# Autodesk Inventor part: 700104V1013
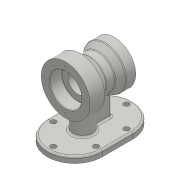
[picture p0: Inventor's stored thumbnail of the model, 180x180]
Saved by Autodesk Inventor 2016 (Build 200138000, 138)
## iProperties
Created: 2020-01
Part Number: 700104V1013
Material: Generic
Document SubType Name: Modeling
Designer: woori
Density: 1 g/cm^3
Appearance: Default
Author: woori
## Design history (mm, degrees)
sketch "스케치1"
  geometry: L1 (-25, 0)-(25, 0); L2 (-25, -45)-(25, -45); L3 (25, 45)-(-25, 45); A1 r 45 centre (-25, 0) between (-25, 45) and (-25, -45); A2 r 45 centre (25, 0) between (25, -45) and (25, 45); 2 further points
  constraints: 8 end point, 4 point on circle, 4 tangent, 2 centre point, 1 coincident, 1 horizontal, 1 midpoint, 1 parallel
  dimensions: "d0" = 50 distance of L3.start L3.end; "d1" = 45 radius of A1
extrude "돌출1" new body sketch "스케치1" distance "d2" = 10; taper "d3" = 0 deg
sketch "스케치2"
  geometry: L1 (0, 80)-(0, 0); L2 (0, 80)-(40, 80); L3 (40, 80)-(40, 115); L4 (40, 115)-(24, 115); L5 (24, 115)-(13.289, 107.5); L6 (13.289, 107.5)-(-1.103, 107.5); L7 (-1.103, 107.5)-(-16, 120); L8 (-16, 120)-(-40, 120); L9 (-40, 120)-(-40, 80); L10 (-40, 80)-(0, 80); L11 (-25, 0)-(-70, 0) reference; L12 (-70, 0)-(-70, 19.736)
  constraints: 22 end point, 4 perpendicular, 2 parallel, 2 vertical, 1 horizontal, 1 point on line
  dimensions: "d4" = 80 distance of L1.start L1.end; "d5" = 35 deg angle of L6 L5; "d6" = 40 deg angle of L6 L7; "d7" = 16 distance of L3.end L4.end; "d8" = 24 distance of L7.end L8.end; "d9" = 80 distance between parallel lines of L3 L9; "d10" = 55 diameter of L6 L10; "d11" = 80 diameter of L8 L10; "d12" = 70 diameter of L4 L2; "d13" = 30 distance between parallel lines of L12 L9
sketch "스케치3"
  geometry: L1 (-25, -45)-(25, -45) reference; L2 (25, 45)-(-25, 45) reference; L3 (0, 0)-(70, 0); A1 r 45 centre (25, 0) between (25, -45) and (25, 45) reference; A2 r 45 centre (-25, 0) between (-25, 45) and (-25, -45) reference
  constraints: 2 end point, 1 point on circle
revolve "회전1" stored, may be unused: angle "d14" = 90 deg
sketch "스케치4"
  geometry: L1 (23.814, -5)-(-30, -5); L2 (-30, -5)-(-30, 5); L3 (-30, 5)-(23.814, 5); L4 (23.814, 5)-(23.814, -5); L5 (23.814, -5)-(-30, 5); L6 (-30, -5)-(23.814, 5); L7 (12, 0)-(70, 0); C1 r 16 at (12, 0); A1 r 45 centre (25, 0) between (25, -45) and (25, 45) reference; 4 further points
  constraints: 14 end point, 4 midpoint, 2 parallel, 1 centre point, 1 horizontal, 1 horizontal alignment, 1 perpendicular, 1 point on circle
  dimensions: "d15" = 58 distance of L7.end L7.start; "d16" = 10 distance between parallel lines of L3 L1; "d17" = 32 diameter of C1; "d18" = 100 distance from line of L7.end L2
extrude "돌출2" join sketch "스케치4" stored distance "d19" = 10; taper "d20" = 0 deg
sketch "스케치5"
  geometry: L1 (-24.855, 0)-(25.145, 0); L2 (-24.855, -35)-(25.145, -35); L3 (25.145, 35)-(-24.855, 35); A1 r 35 centre (-24.855, 0) between (-24.855, 35) and (-24.855, -35); A2 r 35 centre (25.145, 0) between (25.145, -35) and (25.145, 35); 8 further points
  constraints: 8 end point, 6 point on circle, 4 coincident, 4 tangent, 2 centre point, 1 horizontal, 1 midpoint, 1 parallel
  dimensions: "d21" = 50 distance of L3.start L3.end; "d22" = 35 radius of A1
hole "구멍1" sketch "스케치5" at (-24.855, 35), (25.145, 35), (25.145, -35), (-24.855, -35), (-59.855, 0), (60.145, 0) diameter "d23" = 9; stored, may be unused: countersink angle "d27" = 90 deg, drill point angle "d29" = 0 deg; dims "d24" = 6, "d25" = 4, "d26" = 2, "d28" = 6
fillet "모깎기1" dims "d30" = 3
fillet "모깎기2" dims "d31" = 3
fillet "모깎기3" dims "d32" = 3
sketch "스케치6"
  geometry: L1 (-40, 40)-(-40, 120) reference; L2 (-40, 80)-(-20, 80); L3 (-20, 80)-(-20, 106); L4 (-20, 106)-(-40, 106); L5 (-40, 106)-(-40, 80); L6 (-20, 80)-(23, 80); L7 (23, 80)-(23, 96); L8 (23, 96)-(-20, 96); L9 (-20, 96)-(-20, 80); L10 (40, 45)-(40, 115) reference; L11 (23, 80)-(40, 80); L12 (40, 80)-(40, 100); L13 (40, 100)-(23, 100); L14 (23, 100)-(23, 80); 1 further point
  constraints: 24 end point, 6 parallel, 3 horizontal, 3 perpendicular, 1 midpoint, 1 point on line
  dimensions: "d33" = 52 diameter of L4 L2; "d34" = 32 diameter of L8 L6; "d35" = 40 diameter of L13 L11; "d36" = 20 distance between parallel lines of L1 L3; "d37" = 17 distance between parallel lines of L10 L7
revolve "회전2" sketch "스케치6" stored, may be unused: angle "d38" = 90 deg
fillet "모깎기4" dims "d39" = 0.3
chamfer "모따기1" distance "d40" = 1; stored, may be unused: second distance "d41" = 2, angle "d42" = 45 deg
fillet "모깎기5" dims "d43" = 3
sketch "스케치7" dims "d44" = 66
  geometry: C1 r 27 at (0, 0) reference; 3 further points
  constraints: 1 coincident, 1 horizontal alignment, 2 other
hole "구멍2" sketch "스케치7" at (-33, 0) diameter "d45" = 3.242; stored, may be unused: countersink angle "d49" = 90 deg, drill point angle "d51" = 118 deg; dims "d46" = 9, "d47" = 4, "d48" = 2, "d50" = 11
sketch "스케치8" dims "d55" = 55
  geometry: C1 r 21 at (0, 0) reference; 3 further points
  constraints: 1 coincident, 1 horizontal alignment, 2 other
hole "구멍3" sketch "스케치8" at (27.5, 0) diameter "d56" = 3.242; stored, may be unused: countersink angle "d60" = 90 deg, drill point angle "d62" = 118 deg; dims "d57" = 9, "d58" = 4, "d59" = 2, "d61" = 11
node "솔리드1"
pattern_circular "원형 패턴1" dims angle "d53" = 360 deg
pattern_circular "원형 패턴2" dims angle "d64" = 360 deg
